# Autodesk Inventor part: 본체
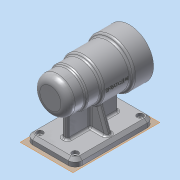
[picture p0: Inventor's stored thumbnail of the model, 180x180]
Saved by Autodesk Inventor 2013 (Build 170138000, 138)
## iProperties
Created: 2016-06
Part Number: 본체
Material: 알루미늄 6061
Document SubType Name: Modeling
Designer: dgall
Density: 2.71 g/cm^3
Mass: 673.897 g
Surface Area: 647.222 cm^2
Volume: 248.67 cm^3
Author: dgall
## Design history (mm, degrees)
sketch "스케치1"
  geometry: L1 (-56, 0)-(56, 0); L2 (-56, 0)-(-56, 25); L3 (-56, 25)-(-31, 25); L4 (-31, 25)-(-31, 27); L5 (-31, 27)-(-11, 27); L6 (-11, 27)-(-11, 30); L7 (-11, 30)-(28, 30); L8 (28, 30)-(28, 34); L9 (28, 34)-(56, 34); L10 (56, 34)-(56, 21); L11 (56, 21)-(41, 21); L12 (41, 21)-(41, 21); L13 (38, 24)-(-10, 24); L14 (-13, 21)-(-13, 21); L15 (-13, 21)-(-24.7, 21); L16 (-25, 20.7)-(-25, 17.5); L17 (-25, 17.5)-(-42.7, 17.5); L18 (-43, 17.2)-(-43, 16); L19 (-43, 16)-(-46.7, 16); L20 (-47, 15.7)-(-47, 10.5); L21 (-47, 10.5)-(-47, 10.5); L22 (-50, 7.5)-(-50, 0); A1 r 3 centre (-10, 21) between (-10, 24) and (-13, 21); A2 r 3 centre (38, 21) between (41, 21) and (38, 24); A3 r 3 centre (-47, 7.5) between (-47, 10.5) and (-50, 7.5); A4 r 0.3 centre (-46.7, 15.7) between (-46.7, 16) and (-47, 15.7); A5 r 0.3 centre (-42.7, 17.2) between (-42.7, 17.5) and (-43, 17.2); A6 r 0.3 centre (-24.7, 20.7) between (-24.7, 21) and (-25, 20.7); 8 further points
  constraints: 44 end point, 15 parallel, 13 point on line, 12 point on circle, 12 tangent, 6 centre point, 5 perpendicular, 4 equal radius, 1 coincident, 1 collinear, 1 horizontal, 1 midpoint, 1 vertical alignment
  dimensions: "d0" = 112 distance of L1.start L1.end; "d2" = 50 diameter of L3 L1; "d3" = 54 diameter of L5 L1; "d4" = 60 diameter of L7 L1; "d5" = 68 diameter of L9 L1; "d6" = 25 distance of L2.end L3.end; "d7" = 45 distance between parallel lines of L6 L2; "d8" = 84 distance between parallel lines of L2 L8; "d9" = 21 diameter of L21 L1; "d10" = 15 distance of L10.end L11.end; "d11" = 42 diameter of L11 L1; "d13" = 48 diameter of L13 L1; "d14" = 54 distance of point (41, 24) point (-13, 24); "d15" = 12 distance of L14.end point (-25, 21); "d16" = 18 distance of L16.end point (-43, 17.5); "d17" = 4 distance of L18.end point (-47, 16); "d18" = 3 distance of L20.end point (-50, 10.5); "d19" = 32 diameter of L19 L1; "d20" = 35 diameter of L17 L1; "d21" = 42 diameter of L15 L1; "d25" = 3 radius of A1; "d26" = 0.3 radius of A4
revolve "회전1" sketch "스케치1" stored, may be unused: angle "d22" = 90 deg
fillet "모깎기1" dims "d23" = 10, "d24" = 3
node "작업 평면1"
sketch "스케치2"
  geometry: L1 (-25, 56)-(25, 56); L2 (35, 46)-(35, -46); L3 (25, -56)-(-25, -56); L4 (-35, -46)-(-35, 46); L5 (-4, 36)-(4, 36); L6 (4, 36)-(4, -36); L7 (4, -36)-(-4, -36); L8 (-4, -36)-(-4, 36); A1 r 10 centre (-25, 46) between (-25, 56) and (-35, 46); A2 r 10 centre (-25, -46) between (-35, -46) and (-25, -56); A3 r 10 centre (25, -46) between (25, -56) and (35, -46); A4 r 10 centre (25, 46) between (35, 46) and (25, 56); 8 further points
  constraints: 16 end point, 8 point on circle, 8 tangent, 6 point on line, 4 centre point, 4 midpoint, 4 parallel, 3 equal radius, 2 horizontal, 2 horizontal alignment, 2 perpendicular, 2 vertical alignment
  dimensions: "d28" = 112 distance of point (35, 56) point (35, -56); "d30" = 70 distance of point (-35, 56) point (35, 56); "d31" = 10 radius of A1; "d32" = 8 distance of L5.start L5.end; "d33" = 20 distance from line of point (0, 36) L1
extrude "돌출1" join sketch "스케치2" distance "d34" = 10; taper "d35" = 0 deg
extrude "돌출2" join sketch "스케치2" stored distance "d36" = 10; taper "d37" = 0 deg
sketch "스케치3"
  geometry: L1 (-25, -60)-(25, -60) reference; L2 (-25, -60)-(-35, -60) reference; L3 (-28, -60)-(-15.509, -25.68); L4 (-35, -70)-(-35, -60) reference; A1 r 30 centre (0, 0) between (4, -29.732) and (-4, -29.732) reference; 1 further point
  constraints: 2 end point, 1 point on circle, 1 point on line
  dimensions: "d38" = 7 distance from line of L4 L3.start; "d39" = 110 deg angle of L3 L2
feature "리브1" sketch "스케치3" dims "d40" = 1, "d41" = 8, "d42" = 0, "d43" = 0, "d44" = 1, "d45" = 1
sketch "스케치4"
  geometry: C1 r 21 at (0, 0) reference; 1 further point
  constraints: 1 vertical alignment
  dimensions: "d46" = 26 distance of C1.centre point (0, -26)
hole "구멍1" sketch "스케치4" at (0, -26) diameter "d47" = 3.242; stored, may be unused: countersink angle "d51" = 90 deg, drill point angle "d53" = 118 deg; dims "d48" = 8, "d49" = 4, "d50" = 2, "d52" = 11
chamfer "모따기1" distance "d57" = 4; stored, may be unused: second distance "d58" = 2, angle "d59" = 45 deg
hole "구멍2" diameter "d62" = 5; stored, may be unused: countersink angle "d66" = 90 deg, drill point angle "d68" = 118 deg; dims "d60" = 10, "d61" = 10, "d63" = 8, "d64" = 9, "d65" = 4, "d67" = 11
fillet "모깎기2" dims "d69" = 3
fillet "모깎기3" dims "d70" = 3
node "작업 평면2"
sketch "스케치5"
  geometry: L1 (47.5, -34)-(47.5, 34) reference; 2 further points
  constraints: 1 horizontal alignment, 1 other
  dimensions: "d71" = 48 distance from line of L1 point (-0.5, 0)
feature "엠보싱1" sketch "스케치5" dims "d18" = 3, "d72" = 0.5, "d73" = 0
chamfer "모따기2" distance "d74" = 1; stored, may be unused: second distance "d75" = 2, angle "d76" = 45 deg
node "솔리드1"
mirror "대칭1"
pattern_circular "원형 패턴1" dims angle "d55" = 360 deg
mirror "대칭2"
mirror "대칭3"
